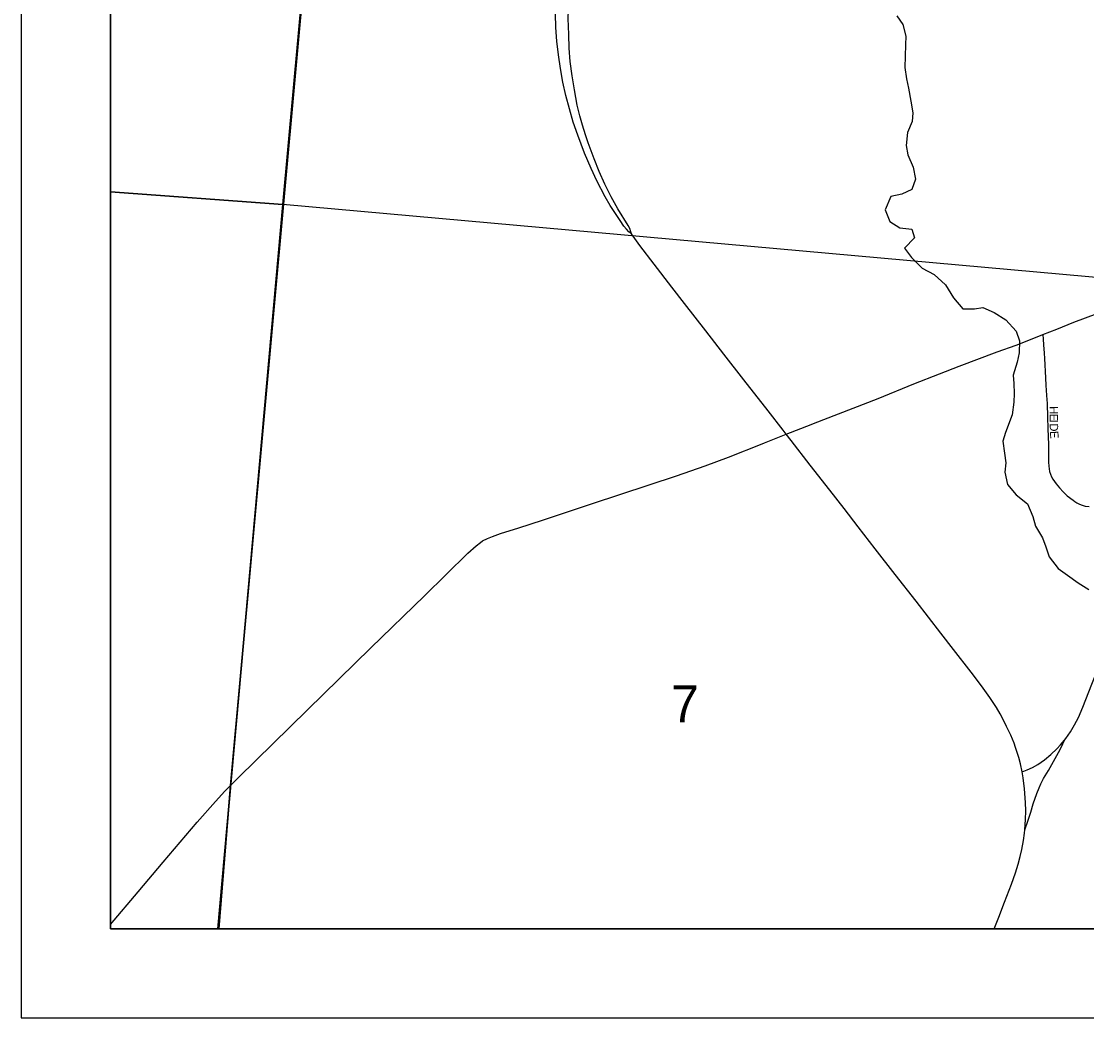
# Model space of a CAD drawing. Extents: x -209 to 4852, y 0 to 905.
# Drawn here: x 57.34 to 81.27, y 200.56 to 222.94 of the extents above; entities that cross this region are included whole.
import ezdxf

# ---------------------------------------------------------------- set-up
doc = ezdxf.new("R2010")
doc.units = 0
for name, color, linetype in [('Default', 7, 'Continuous'), ('GM_X_Corporation', 7, 'Continuous'), ('GM_X_County_Road', 7, 'Continuous'), ('GM_X_County_Road_Text', 7, 'Continuous'), ('GM_X_Interstate_Location', 7, 'Continuous'), ('GM_X_Minor_Lake_Text', 7, 'Continuous'), ('GM_X_Minor_River', 7, 'Continuous'), ('GM_X_Township_Road_Text', 7, 'Continuous'), ('GM_X_Township_Text', 7, 'Continuous'), ('SH_Data', 7, 'Continuous')]:
    doc.layers.add(name, color=color, linetype=linetype)

msp = doc.modelspace()

# ---------------------------------------------------------------- linework, layer by layer
at = {"layer": 'Default'}
for points in [[(59.342, 338.559), (195.342, 338.559), (195.342, 202.559), (59.342, 202.559)], [(195.342, 202.559), (195.342, 338.559), (59.342, 338.559), (59.342, 202.559)]]:
    msp.add_lwpolyline(points, close=True, dxfattribs=at)
at = {"layer": 'GM_X_Corporation'}
msp.add_line((79.19, 202.559), (79.292, 202.817), dxfattribs=at)
for points in [[(71.045, 218.165), (71.025, 218.234), (71.012, 218.276), (70.97, 218.359), (70.735, 218.729), (70.586, 219.002), (70.449, 219.282), (70.323, 219.567), (70.207, 219.856), (70.072, 220.213), (70.009, 220.394), (69.947, 220.611), (69.888, 220.821), (69.829, 221.061), (69.763, 221.407), (69.71, 221.719), (69.671, 222.041), (69.648, 222.34), (69.635, 222.643), (69.625, 223.005), (69.635, 223.379), (69.664, 223.886), (69.735, 224.639), (69.773, 225.108)], [(71.045, 218.165), (70.983, 218.214), (70.93, 218.27), (70.874, 218.342), (70.789, 218.47), (70.684, 218.628), (70.568, 218.806), (70.457, 218.996), (70.269, 219.356), (70.137, 219.636), (69.992, 219.978), (69.838, 220.384), (69.738, 220.677), (69.65, 220.974), (69.573, 221.274), (69.505, 221.577), (69.45, 221.881), (69.405, 222.188), (69.372, 222.496), (69.35, 222.805), (69.339, 223.114)], [(74.449, 213.76), (74.113, 214.192), (73.57, 214.886), (73.12, 215.465), (72.712, 215.991), (72.235, 216.606), (71.953, 216.974), (71.558, 217.487), (71.236, 217.905), (71.045, 218.165)], [(79.292, 202.817), (79.425, 203.151), (79.58, 203.558), (79.672, 203.814), (79.731, 204.005), (79.777, 204.183), (79.809, 204.335), (79.846, 204.541), (79.87, 204.704), (79.881, 204.783), (79.897, 205.015), (79.902, 205.203), (79.895, 205.39), (79.87, 205.701), (79.839, 205.949), (79.819, 206.086), (79.781, 206.261), (79.742, 206.407), (79.699, 206.541), (79.671, 206.628), (79.636, 206.727), (79.561, 206.906), (79.469, 207.103), (79.395, 207.255), (79.325, 207.389), (79.242, 207.531), (79.094, 207.754), (78.907, 208.017), (78.674, 208.32), (78.276, 208.833), (77.99, 209.201), (77.437, 209.915), (76.967, 210.516), (76.52, 211.095), (76.138, 211.588), (75.82, 211.996), (75.497, 212.41), (75.057, 212.973), (74.632, 213.525), (74.522, 213.666), (74.449, 213.76)]]:
    msp.add_lwpolyline(points, dxfattribs=at)
at = {"layer": 'GM_X_County_Road'}
for points in [[(77.001, 223.067), (77.136, 222.869), (77.209, 222.611), (77.2, 222.414), (77.191, 222.156), (77.181, 221.906), (77.225, 221.648), (77.269, 221.443), (77.319, 221.147), (77.363, 220.889), (77.346, 220.692), (77.246, 220.442), (77.214, 220.154), (77.25, 219.942), (77.369, 219.668)], [(77.369, 219.668), (77.42, 219.394), (77.343, 219.167), (77.115, 219.063), (76.872, 219.004), (76.741, 218.709), (76.845, 218.443), (77.071, 218.305), (77.343, 218.273), (77.402, 218.075), (77.174, 217.849), (77.331, 217.636), (77.571, 217.399), (77.843, 217.253), (78.098, 217.024), (78.278, 216.734), (78.488, 216.482), (78.745, 216.48), (78.934, 216.517), (79.191, 216.401), (79.454, 216.24), (79.687, 215.981), (79.761, 215.768), (79.751, 215.495), (79.704, 215.283), (79.619, 214.995), (79.633, 214.806), (79.638, 214.578), (79.629, 214.389), (79.597, 214.101), (79.443, 213.708), (79.388, 213.511), (79.424, 213.238), (79.453, 213.025), (79.428, 212.813), (79.487, 212.54), (79.682, 212.303), (79.938, 212.104), (80.057, 211.815), (80.116, 211.602), (80.272, 211.336), (80.347, 211.138), (80.428, 210.91), (80.63, 210.651), (80.834, 210.497), (81.074, 210.329), (81.315, 210.175)]]:
    msp.add_lwpolyline(points, dxfattribs=at)
at = {"layer": 'GM_X_County_Road_Text'}
for points in [[(80.77, 206.794), (80.798, 206.83), (80.903, 206.982), (80.997, 207.141), (81.082, 207.306), (81.181, 207.532), (81.386, 208.052), (81.809, 209.128), (82.139, 209.965), (82.612, 211.181), (82.879, 211.877), (83.172, 212.629), (83.375, 213.149), (83.761, 214.132), (84.191, 215.23), (84.393, 215.751), (84.821, 216.851), (85.148, 217.695)], [(80.282, 215.906), (80.594, 216.03), (80.982, 216.181), (81.505, 216.381), (82.082, 216.608), (82.327, 216.704)], [(75.081, 213.884), (75.135, 213.905), (76.582, 214.472), (77.389, 214.796), (77.966, 215.026), (78.403, 215.193), (79.261, 215.518), (79.687, 215.666), (80.042, 215.811), (80.282, 215.906)], [(73.982, 213.454), (74.035, 213.475), (74.522, 213.666)], [(74.522, 213.666), (75.081, 213.884)], [(62.031, 205.766), (62.039, 205.774), (62.218, 205.953), (63.773, 207.474), (65.193, 208.867), (66.395, 210.038), (66.883, 210.517), (67.372, 210.995), (67.554, 211.163), (67.651, 211.237), (67.702, 211.269), (67.811, 211.325), (67.925, 211.372), (68.1, 211.435), (68.514, 211.567), (69.048, 211.735), (70.169, 212.107), (72.056, 212.733), (72.702, 212.958), (73.226, 213.154), (73.982, 213.454)], [(79.819, 206.086), (79.933, 206.127), (80.048, 206.179), (80.169, 206.246), (80.32, 206.353), (80.463, 206.47), (80.599, 206.596), (80.682, 206.686), (80.77, 206.794)], [(79.881, 204.783), (79.957, 205), (80.013, 205.174), (80.069, 205.361), (80.148, 205.598), (80.198, 205.723), (80.236, 205.812), (80.299, 205.93), (80.407, 206.114), (80.638, 206.515), (80.693, 206.627), (80.77, 206.794)], [(59.342, 202.653), (59.964, 203.387), (60.527, 204.051), (61.293, 204.95), (61.7, 205.419), (61.911, 205.646), (62.031, 205.766)]]:
    msp.add_lwpolyline(points, dxfattribs=at)
at = {"layer": 'GM_X_Minor_Lake_Text'}
msp.add_lwpolyline([(59.342, 300.452), (59.342, 264.57), (60.024, 264.424), (61.555, 264.195), (62.287, 263.967), (63.11, 263.99), (64.161, 263.807), (64.71, 263.579), (65.099, 263.51), (66.173, 263.396), (66.47, 263.327), (67.328, 262.997), (67.133, 261.449), (67.026, 260.458), (66.046, 249.36), (65.411, 242.655), (64.751, 235.526), (64.741, 235.424), (64.703, 235.009), (64.697, 234.939), (62.039, 205.774), (61.776, 202.559), (195.342, 202.559)], dxfattribs=at)
msp.add_lwpolyline([(59.342, 264.57), (59.342, 202.559), (61.776, 202.559), (62.039, 205.774), (64.697, 234.939), (64.703, 235.009), (64.741, 235.424), (64.751, 235.526), (65.411, 242.655), (66.046, 249.36), (67.026, 260.458), (67.133, 261.449), (67.328, 262.997), (66.47, 263.327), (66.173, 263.396), (65.099, 263.51), (64.71, 263.579), (64.161, 263.807), (63.11, 263.99), (62.287, 263.967), (61.555, 264.195), (60.024, 264.424)], close=True, dxfattribs=at)
at = {"layer": 'GM_X_Minor_River'}
for points in [[(59.342, 239.357), (59.342, 219.113), (63.212, 218.824), (65.048, 238.898)], [(65.048, 238.898), (84.904, 237.096), (83.068, 217.043), (63.212, 218.824)], [(59.342, 219.113), (59.342, 202.559), (61.756, 202.559), (63.212, 218.824)], [(61.756, 202.559), (81.8, 202.559), (83.068, 217.043), (63.212, 218.824)]]:
    msp.add_lwpolyline(points, close=True, dxfattribs=at)
at = {"layer": 'GM_X_Township_Text'}
msp.add_lwpolyline([(80.282, 215.906), (80.29, 215.799), (80.299, 215.675), (80.315, 215.49), (80.323, 215.365), (80.341, 214.935), (80.354, 214.759), (80.361, 214.656), (80.368, 214.54), (80.379, 214.357), (80.39, 214.047), (80.398, 213.798), (80.407, 213.426), (80.413, 213.238), (80.413, 213.036), (80.419, 212.949), (80.422, 212.889), (80.434, 212.828), (80.453, 212.769), (80.479, 212.712), (80.509, 212.658), (80.542, 212.605), (80.579, 212.555), (80.657, 212.46), (80.742, 212.37), (80.833, 212.285), (80.963, 212.185), (81.001, 212.156), (81.05, 212.127), (81.11, 212.096), (81.166, 212.074), (81.233, 212.054), (81.324, 212.04)], dxfattribs=at)
at = {"layer": 'SH_Data'}
for p, q in [((57.342, 340.559), (57.342, 200.559)), ((57.342, 200.559), (197.342, 200.559))]:
    msp.add_line(p, q, dxfattribs=at)

# ---------------------------------------------------------------- texts
at = {"layer": 'GM_X_Interstate_Location'}
for s, rotation, p in [('H', 270.2404, (80.435, 214.296)), ('E', 270.254, (80.436, 214.129)), ('I', 270.2186, (80.437, 213.996)), ('D', 271.3931, (80.437, 213.909)), ('E', 273.8582, (80.441, 213.733))]:
    msp.add_text(s, height=0.189, rotation=rotation, dxfattribs=at).set_placement(p)
at = {"layer": 'GM_X_Township_Road_Text'}
msp.add_text('7', height=0.837, rotation=0, dxfattribs=at).set_placement((71.935, 207.191))

doc.saveas('drawing.dxf')
